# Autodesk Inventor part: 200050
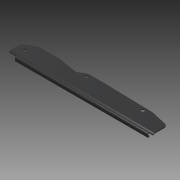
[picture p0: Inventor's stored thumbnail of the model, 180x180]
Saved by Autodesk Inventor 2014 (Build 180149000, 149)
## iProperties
Created: 2007-10
Part Number: 200050
Document SubType Name: Modeling
Designer: TH
Density: 7.85 g/cm^3
Mass: 510.334 g
Surface Area: 671.811 cm^2
Volume: 65.0106 cm^3
Material: Steel
Description: RAIL SIDE - LEFT INNER
Appearance: Dark Gray
Component Category: Lower Component
Author: TH
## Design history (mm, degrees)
sketch "Sketch1"
  geometry: L1 (0, -50.842)-(0, -19.842); L2 (0, -19.842)-(35, 0); L3 (35, 0)-(94, 0); L4 (94, 0)-(157, -9.978); L5 (157, -9.978)-(181, 4); L6 (181, 4)-(221, 4); L7 (221, 4)-(380, 0); L8 (380, 0)-(437, -12.842); L9 (0, -50.842)-(437, -50.842); L10 (0, 14.968)-(0, -61.811) reference; L11 (-87.4, 0)-(524.4, 0) reference; L12 (437, -50.842)-(437, -12.842); 1 further point
  constraints: 20 end point, 2 collinear, 2 point on line, 1 parallel, 1 perpendicular
  dimensions: "d0" = 50.84228 distance from line of point (0, 0) L9; "d1" = 31 distance of L1.start L1.end; "d2" = 35 distance of L2.end point (0, 0); "d3" = 59 distance of L2.end L3.end; "d4" = 9 deg angle of L3 L4; "d8" = 4 distance between parallel lines of L6 L3; "d9" = 40 distance of L5.end L6.end; "d12" = 38 distance of L9.end L8.end; "d13" = 57 distance from line of L7.end L12; "d14" = 437 distance between parallel lines of L12 L1; "d15" = 63 horizontal distance of L3.end L4.end; "d16" = 24 horizontal distance of L5.end L4.end
extrude "Extrusion1" new body sketch "Sketch1" distance "d17" = 2; taper "d18" = 0 deg
fillet "Fillet1" dims "d19" = 12
sketch "Sketch2"
  geometry: L1 (0, 24.009)-(0, 0) reference; L2 (2, 0)-(0, 0) reference; L3 (2, 24.009)-(2, 0) reference; L4 (0, 0)-(0, 0); L5 (-2, -4.472)-(-2, -6.75); L6 (-4, -8.75)-(-9, -8.75); L7 (-11, -6.75)-(-11, -1.3); L8 (-11, -1.3)-(-13, -1.3); L9 (-13, -1.3)-(-13, -6.75); L10 (-9, -10.75)-(-4, -10.75); L11 (0, -6.75)-(0, -4.472); L12 (0, -4)-(-2, -4); L13 (2, 0)-(2, 0); A1 r 4 centre (-2, 0) between (0.667, -2.981) and (2, 0); A2 r 2 centre (2, -4.472) between (0.667, -2.981) and (0, -4.472); A3 r 2 centre (-2, 0) between (-0.667, -1.491) and (0, 0); A4 r 4 centre (2, -4.472) between (-0.667, -1.491) and (-2, -4.472); A5 r 2 centre (-4, -6.75) between (-4, -8.75) and (-2, -6.75); A6 r 2 centre (-9, -6.75) between (-11, -6.75) and (-9, -8.75); A7 r 4 centre (-9, -6.75) between (-13, -6.75) and (-9, -10.75); A8 r 4 centre (-4, -6.75) between (-4, -10.75) and (0, -6.75); 1 further point
  constraints: 20 end point, 17 point on circle, 15 tangent, 8 centre point, 5 parallel, 2 collinear, 1 equal radius, 1 point on line
  dimensions: "d21" = 2 distance between parallel lines of L5 L11; "d22" = 2 distance between parallel lines of L10 L6 (= d21); "d23" = 2 distance between parallel lines of L9 L7 (= d21); "d24" = 9 distance between parallel lines of L7 L5; "d25" = 4.75 distance between parallel lines of L6 L12; "d26" = 4 distance between parallel lines of L2 L12; "d27" = 4 radius of A1; "d28" = 4 radius of A7; "d31" = 2 radius of A2; "d32" = 4 radius of A4; "d33" = 2 radial gap between concentric circles of A3 A1; "d34" = 2 radius of A3; "d35" = 2 radius of A5; "d36" = 2 radius of A6
extrude "Extrusion2" join sketch "Sketch2" distance "d29" = 437; taper "d30" = 0 deg
sketch "Sketch3"
  geometry: L1 (-2, -28.481)-(-2, -30.759) reference; L2 (-4, -32.759)-(-9, -32.759) reference; L3 (-11, -30.759)-(-11, -25.309) reference; L4 (-11, -25.309)-(-13, -25.309) reference; L5 (-13, -25.309)-(-13, -30.759) reference; L6 (-9, -34.759)-(-4, -34.759) reference; L7 (0, -30.759)-(0, -28.481) reference; L8 (0, -29.62)-(-2, -29.62); A1 r 2 centre (-4, -30.759) between (-4, -32.759) and (-2, -30.759) reference; A2 r 2 centre (-9, -30.759) between (-11, -30.759) and (-9, -32.759) reference; A3 r 4 centre (-9, -30.759) between (-13, -30.759) and (-9, -34.759) reference; A4 r 4 centre (-4, -30.759) between (-4, -34.759) and (0, -30.759) reference; 1 further point
  constraints: 2 end point, 2 midpoint
extrude "Extrusion3" cut sketch "Sketch3" distance "d37" = 23; taper "d38" = 0 deg
fillet "Fillet2" dims "d39" = 2
fillet "Fillet3" dims "d40" = 4
sketch "Sketch4"
  geometry: L1 (2, -35.153)-(2, -32.875) reference; L2 (11, -39.153)-(6, -39.153) reference; L3 (15, -29.703)-(15, -35.153) reference; L4 (13, -29.703)-(15, -29.703) reference; L5 (13, -35.153)-(13, -29.703) reference; L6 (6, -37.153)-(11, -37.153) reference; L7 (4, -32.875)-(4, -35.153) reference; L8 (2, -34.014)-(4, -34.014); A1 r 4 centre (6, -35.153) between (2, -35.153) and (6, -39.153) reference; A2 r 4 centre (11, -35.153) between (11, -39.153) and (15, -35.153) reference; A3 r 2 centre (11, -35.153) between (11, -37.153) and (13, -35.153) reference; A4 r 2 centre (6, -35.153) between (4, -35.153) and (6, -37.153) reference; 1 further point
  constraints: 2 end point, 2 midpoint
extrude "Extrusion4" cut sketch "Sketch4" distance "d41" = 12; taper "d42" = 0 deg
fillet "Fillet4" dims "d43" = 4
fillet "Fillet5" dims "d44" = 2
sketch "Sketch5"
  geometry: 4 further points
  dimensions: "d45" = 30.55 vertical distance of point (0, 0) point (21.897, -30.55); "d46" = 21.897 horizontal distance of point (0, 0) point (21.897, -30.55); "d47" = 185.717 horizontal distance of point (185.717, -6.53) point (0, 0); "d48" = 6.53 vertical distance of point (0, 0) point (185.717, -6.53); "d49" = 360.08 horizontal distance of point (360.08, -9.67) point (0, 0); "d50" = 9.67 vertical distance of point (0, 0) point (360.08, -9.67)
hole "Hole1" sketch "Sketch5" diameter "d51" = 10; stored, may be unused: countersink angle "d55" = 90 deg, drill point angle "d57" = 118 deg; dims "d52" = 6, "d53" = 4, "d54" = 2, "d56" = 8
hole "Hole2" sketch "Sketch5" diameter "d58" = 8.15; stored, may be unused: countersink angle "d62" = 90 deg, drill point angle "d64" = 118 deg; dims "d59" = 6, "d60" = 4, "d61" = 2, "d63" = 8
body "Solid1"
